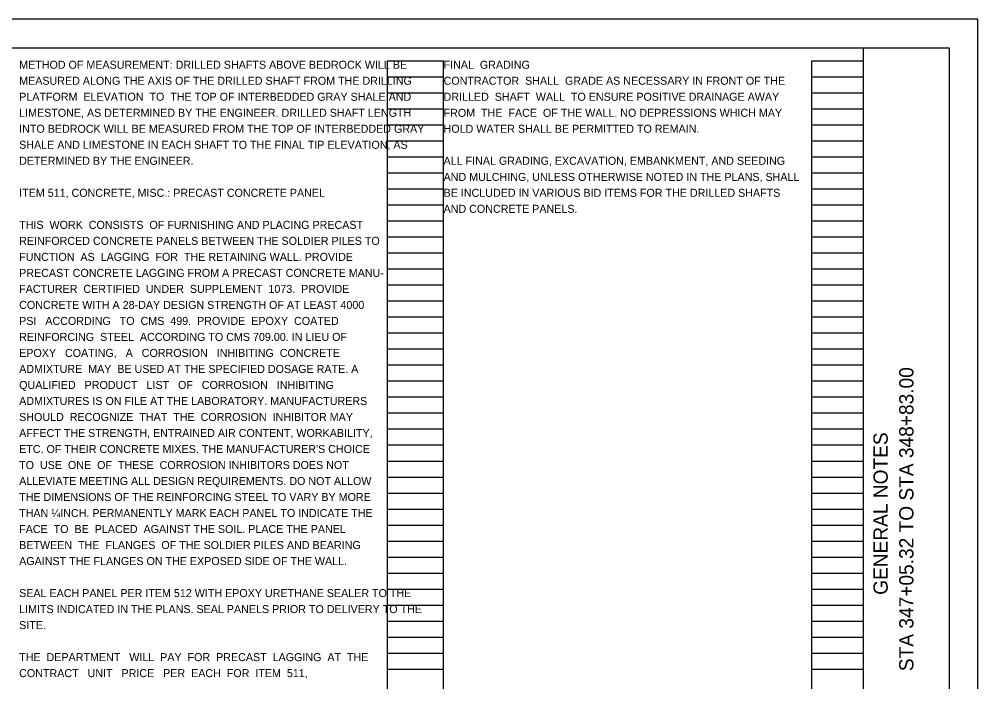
# Model space of a CAD drawing. Extents: x -0.5 to 34, y 0 to 22.
# Drawn here: x 17.24 to 34, y 10.41 to 22 of the extents above; entities that cross this region are included whole.
import ezdxf

# ---------------------------------------------------------------- set-up
doc = ezdxf.new("R2010")
doc.units = 0
for name, color, linetype in [('SH_Border', 7, 'Continuous'), ('SH_Cut_Line', 7, 'Continuous'), ('SH_Data', 7, 'Continuous'), ('SH_Text', 7, 'Continuous')]:
    doc.layers.add(name, color=color, linetype=linetype)

msp = doc.modelspace()

# ---------------------------------------------------------------- linework, layer by layer
at = {"layer": 'SH_Border'}
msp.add_line((32, 0.5), (32, 21.5), dxfattribs=at)
msp.add_lwpolyline([(1.5, 21.5), (33.5, 21.5), (33.5, 0.5), (1.5, 0.5)], close=True, dxfattribs=at)
at = {"layer": 'SH_Cut_Line'}
msp.add_lwpolyline([(0, 0), (34, 0), (34, 22), (0, 22)], close=True, dxfattribs=at)
at = {"layer": 'SH_Data'}
for p, q in [((23.68, 1.113), (23.68, 21.273)), ((23.68, 21.273), (24.66, 21.273)), ((24.66, 1.113), (24.66, 21.273)), ((31.1, 1.113), (31.1, 21.273)), ((31.1, 21.273), (32, 21.273)), ((32, 1.113), (32, 21.273)), ((23.68, 20.993), (24.66, 20.993)), ((31.1, 20.993), (32, 20.993)), ((23.68, 20.713), (24.66, 20.713)), ((31.1, 20.713), (32, 20.713)), ((23.68, 20.433), (24.66, 20.433)), ((31.1, 20.433), (32, 20.433)), ((23.68, 20.153), (24.66, 20.153)), ((31.1, 20.153), (32, 20.153)), ((23.68, 19.873), (24.66, 19.873)), ((31.1, 19.873), (32, 19.873)), ((23.68, 19.593), (24.66, 19.593)), ((31.1, 19.593), (32, 19.593)), ((23.68, 19.313), (24.66, 19.313)), ((31.1, 19.313), (32, 19.313)), ((23.68, 19.033), (24.66, 19.033)), ((31.1, 19.033), (32, 19.033)), ((23.68, 18.753), (24.66, 18.753)), ((31.1, 18.753), (32, 18.753)), ((23.68, 18.473), (24.66, 18.473)), ((31.1, 18.473), (32, 18.473)), ((23.68, 18.193), (24.66, 18.193)), ((31.1, 18.193), (32, 18.193)), ((23.68, 17.913), (24.66, 17.913)), ((31.1, 17.913), (32, 17.913)), ((23.68, 17.633), (24.66, 17.633)), ((31.1, 17.633), (32, 17.633)), ((23.68, 17.353), (24.66, 17.353)), ((31.1, 17.353), (32, 17.353)), ((23.68, 17.073), (24.66, 17.073)), ((31.1, 17.073), (32, 17.073)), ((23.68, 16.793), (24.66, 16.793)), ((31.1, 16.793), (32, 16.793)), ((23.68, 16.513), (24.66, 16.513)), ((31.1, 16.513), (32, 16.513)), ((23.68, 16.233), (24.66, 16.233)), ((31.1, 16.233), (32, 16.233)), ((23.68, 15.953), (24.66, 15.953)), ((31.1, 15.953), (32, 15.953)), ((23.68, 15.673), (24.66, 15.673)), ((31.1, 15.673), (32, 15.673)), ((23.68, 15.393), (24.66, 15.393)), ((31.1, 15.393), (32, 15.393)), ((23.68, 15.113), (24.66, 15.113)), ((31.1, 15.113), (32, 15.113)), ((23.68, 14.833), (24.66, 14.833)), ((31.1, 14.833), (32, 14.833)), ((23.68, 14.553), (24.66, 14.553)), ((31.1, 14.553), (32, 14.553)), ((23.68, 14.273), (24.66, 14.273)), ((31.1, 14.273), (32, 14.273)), ((23.68, 13.993), (24.66, 13.993)), ((31.1, 13.993), (32, 13.993)), ((23.68, 13.713), (24.66, 13.713)), ((31.1, 13.713), (32, 13.713)), ((23.68, 13.433), (24.66, 13.433)), ((31.1, 13.433), (32, 13.433)), ((23.68, 13.153), (24.66, 13.153)), ((31.1, 13.153), (32, 13.153)), ((23.68, 12.873), (24.66, 12.873)), ((31.1, 12.873), (32, 12.873)), ((23.68, 12.593), (24.66, 12.593)), ((31.1, 12.593), (32, 12.593)), ((23.68, 12.313), (24.66, 12.313)), ((31.1, 12.313), (32, 12.313)), ((23.68, 12.033), (24.66, 12.033)), ((31.1, 12.033), (32, 12.033)), ((23.68, 11.753), (24.66, 11.753)), ((31.1, 11.753), (32, 11.753)), ((23.68, 11.473), (24.66, 11.473)), ((31.1, 11.473), (32, 11.473)), ((23.68, 11.193), (24.66, 11.193)), ((31.1, 11.193), (32, 11.193)), ((23.68, 10.913), (24.66, 10.913)), ((31.1, 10.913), (32, 10.913)), ((23.68, 10.633), (24.66, 10.633)), ((31.1, 10.633), (32, 10.633))]:
    msp.add_line(p, q, dxfattribs=at)

# ---------------------------------------------------------------- texts
for s, p in [('STA 347+05.32 TO STA 348+83.00', (32.875, 10.598)), ('GENERAL NOTES', (32.425, 11.932))]:
    msp.add_text(s, height=0.25, rotation=90, dxfattribs=at).set_placement(p)
at = {"layer": 'SH_Text'}
for s, p in [('METHOD OF MEASUREMENT: DRILLED SHAFTS ABOVE BEDROCK WILL BE', (17.24, 21.133)), ('FINAL  GRADING', (24.66, 21.133)), ('MEASURED ALONG THE AXIS OF THE DRILLED SHAFT FROM THE DRILLING', (17.24, 20.853)), ('CONTRACTOR  SHALL  GRADE AS NECESSARY IN FRONT OF THE', (24.66, 20.853)), ('PLATFORM  ELEVATION  TO  THE TOP OF INTERBEDDED GRAY SHALE AND', (17.24, 20.573)), ('DRILLED  SHAFT  WALL  TO ENSURE POSITIVE DRAINAGE AWAY', (24.66, 20.573)), ('LIMESTONE, AS DETERMINED BY THE ENGINEER. DRILLED SHAFT LENGTH', (17.24, 20.293)), ('FROM  THE  FACE  OF THE WALL. NO DEPRESSIONS WHICH MAY', (24.66, 20.292)), ('INTO BEDROCK WILL BE MEASURED FROM THE TOP OF INTERBEDDED GRAY', (17.24, 20.013)), ('HOLD WATER SHALL BE PERMITTED TO REMAIN.', (24.66, 20.013)), ('SHALE AND LIMESTONE IN EACH SHAFT TO THE FINAL TIP ELEVATION, AS', (17.24, 19.733)), ('DETERMINED BY THE ENGINEER.', (17.24, 19.453)), ('ALL FINAL GRADING, EXCAVATION, EMBANKMENT, AND SEEDING', (24.66, 19.453)), ('AND MULCHING, UNLESS OTHERWISE NOTED IN THE PLANS, SHALL', (24.66, 19.171)), ('ITEM 511, CONCRETE, MISC.: PRECAST CONCRETE PANEL', (17.24, 18.893)), ('BE INCLUDED IN VARIOUS BID ITEMS FOR THE DRILLED SHAFTS', (24.66, 18.893)), ('AND CONCRETE PANELS.', (24.66, 18.613)), ('THIS  WORK  CONSISTS  OF FURNISHING AND PLACING PRECAST', (17.24, 18.333)), ('REINFORCED CONCRETE PANELS BETWEEN THE SOLDIER PILES TO', (17.24, 18.053)), ('FUNCTION  AS  LAGGING  FOR  THE RETAINING WALL. PROVIDE', (17.24, 17.773)), ('PRECAST CONCRETE LAGGING FROM A PRECAST CONCRETE MANU-', (17.24, 17.493)), ('FACTURER  CERTIFIED  UNDER  SUPPLEMENT  1073.  PROVIDE', (17.24, 17.213)), ('CONCRETE WITH A 28-DAY DESIGN STRENGTH OF AT LEAST 4000', (17.24, 16.933)), ('PSI   ACCORDING   TO  CMS  499.  PROVIDE  EPOXY  COATED', (17.24, 16.653)), ('REINFORCING  STEEL  ACCORDING TO CMS 709.00. IN LIEU OF', (17.24, 16.373)), ('EPOXY   COATING,   A   CORROSION   INHIBITING  CONCRETE', (17.24, 16.093)), ('ADMIXTURE  MAY  BE USED AT THE SPECIFIED DOSAGE RATE. A', (17.24, 15.813)), ('QUALIFIED   PRODUCT   LIST   OF   CORROSION   INHIBITING', (17.24, 15.533)), ('ADMIXTURES IS ON FILE AT THE LABORATORY. MANUFACTURERS', (17.24, 15.253)), ('SHOULD  RECOGNIZE  THAT  THE  CORROSION  INHIBITOR MAY', (17.24, 14.973)), ('AFFECT THE STRENGTH, ENTRAINED AIR CONTENT, WORKABILITY,', (17.24, 14.693)), ("ETC. OF THEIR CONCRETE MIXES. THE MANUFACTURER'S CHOICE", (17.24, 14.413)), ('TO  USE  ONE  OF  THESE  CORROSION INHIBITORS DOES NOT', (17.24, 14.133)), ('ALLEVIATE MEETING ALL DESIGN REQUIREMENTS. DO NOT ALLOW', (17.24, 13.853)), ('THE DIMENSIONS OF THE REINFORCING STEEL TO VARY BY MORE', (17.24, 13.573)), ('THAN ¼INCH. PERMANENTLY MARK EACH PANEL TO INDICATE THE', (17.24, 13.293)), ('FACE  TO  BE  PLACED  AGAINST THE SOIL. PLACE THE PANEL', (17.24, 13.013)), ('BETWEEN  THE  FLANGES  OF THE SOLDIER PILES AND BEARING', (17.24, 12.733)), ('AGAINST THE FLANGES ON THE EXPOSED SIDE OF THE WALL.', (17.24, 12.453)), ('SEAL EACH PANEL PER ITEM 512 WITH EPOXY URETHANE SEALER TO THE', (17.24, 11.893)), ('LIMITS INDICATED IN THE PLANS. SEAL PANELS PRIOR TO DELIVERY TO THE', (17.24, 11.613)), ('SITE.', (17.24, 11.333)), ('THE  DEPARTMENT   WILL  PAY  FOR  PRECAST  LAGGING  AT  THE', (17.24, 10.773)), ('CONTRACT   UNIT   PRICE   PER  EACH  FOR  ITEM  511,', (17.24, 10.493))]:
    msp.add_text(s, height=0.14, dxfattribs=at).set_placement(p)

doc.saveas('drawing.dxf')
